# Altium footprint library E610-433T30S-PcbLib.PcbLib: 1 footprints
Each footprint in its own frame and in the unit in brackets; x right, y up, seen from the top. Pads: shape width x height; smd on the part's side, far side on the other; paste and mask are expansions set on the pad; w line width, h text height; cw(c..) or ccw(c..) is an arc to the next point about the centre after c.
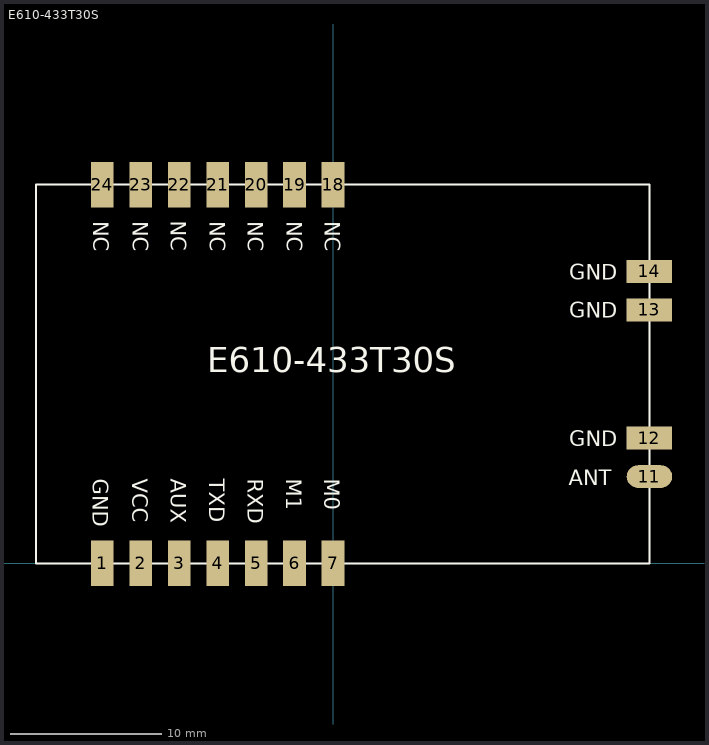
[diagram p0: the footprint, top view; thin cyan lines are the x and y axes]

## E610-433T30S [mm] "40.5mm*25mm*3.80mm-S"
pads (18):
  rect 1.5x3 smd: 1(-15.24,0) 2(-12.7,0) 3(-10.16,0) 4(-7.62,0) 5(-5.08,0) 6(-2.54,0) 7(0,0) 18(0,25) 19(-2.54,25) 20(-5.08,25) 21(-7.62,25) 22(-10.16,25) 23(-12.7,25) 24(-15.24,25)
  oval 3x1.5 smd: 11(20.88,5.73)
  rect 3x1.5 smd: 12(20.88,8.27) 13(20.88,16.73) 14(20.88,19.27)
Top Overlay:
  lines w0.127: -19.62,0 20.88,0 20.88,25 -19.62,25 -19.62,0
  text "NC" at -10.73,22.606 h1
  text "GND" at 15.602,18.73 h1
  text "GND" at 15.602,16.22 h1
  text "NC" at -0.557,22.592 h1
  text "NC" at -3.067,22.592 h1
  text "NC" at -5.617,22.592 h1
  text "NC" at -8.147,22.592 h1
  text "NC" at -13.237,22.592 h1
  text "NC" at -15.827,22.592 h1
  text "GND" at -15.847,5.575 h1
  text "VCC" at -13.257,5.575 h1
  text "AUX" at -10.707,5.575 h1
  text "TXD" at -8.167,5.575 h1
  text "RXD" at -5.637,5.575 h1
  text "M1" at -3.087,5.575 h1
  text "M0" at -0.577,5.575 h1
  text "ANT" at 15.554,5.17 h1
  text "GND" at 15.602,7.72 h1
  text "E610-433T30S" at -8.317,12.065 h2.8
